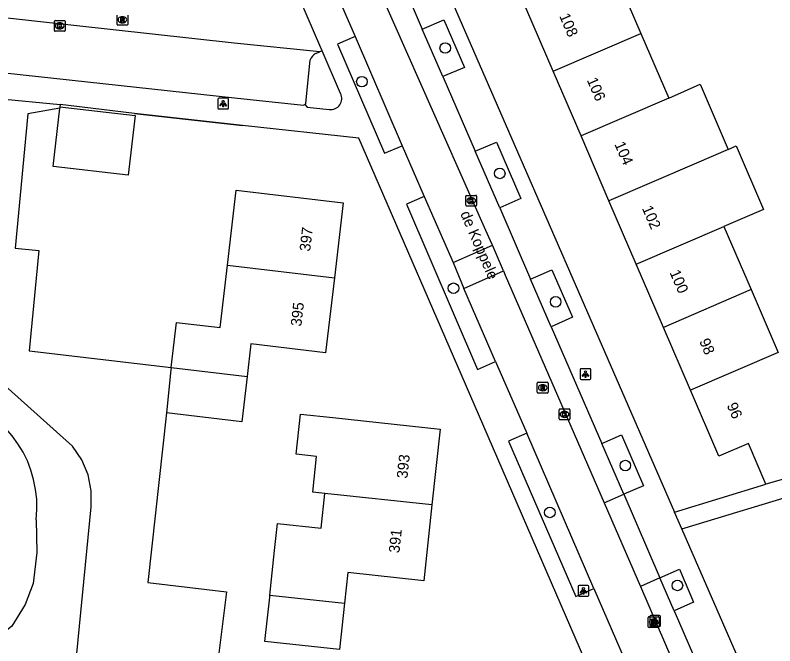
# Model space of a CAD drawing. Extents: x 162026 to 163499, y 387297 to 388169.
# Drawn here: x 162170.5 to 162240.9, y 387854 to 387912.5 of the extents above; entities that cross this region are included whole.
import ezdxf

# ---------------------------------------------------------------- set-up
doc = ezdxf.new("R2010")
doc.units = 0
for name, color, linetype in [('IMGEO_Boom', 7, 'Continuous'), ('IMGEO_Groenvoorziening', 7, 'Continuous'), ('IMGEO_Hek', 7, 'Continuous'), ('IMGEO_Kolk', 7, 'Continuous'), ('IMGEO_Lichtpunt', 7, 'Continuous'), ('IMGEO_Loofbos', 7, 'Continuous'), ('IMGEO_Muur', 7, 'Continuous'), ('IMGEO_Openbare_ruimte_label', 7, 'Continuous'), ('IMGEO_Pand', 7, 'Continuous'), ('IMGEO_Pand_nummerreeks', 7, 'Continuous'), ('IMGEO_Parkeervlak_open', 7, 'Continuous'), ('IMGEO_Rijbaan_lokaal_open', 7, 'Continuous'), ('IMGEO_Rioolput', 7, 'Continuous'), ('IMGEO_Voetpad_open', 7, 'Continuous')]:
    doc.layers.add(name, color=color, linetype=linetype)

msp = doc.modelspace()

# ---------------------------------------------------------------- linework, layer by layer
at = {"layer": 'IMGEO_Boom'}
for centre in [(162210.37, 387909.425), (162202.657, 387906.315), (162215.422, 387897.813), (162211.139, 387887.172), (162220.596, 387885.913), (162227.054, 387870.742), (162220.056, 387866.404), (162231.871, 387859.638)]:
    msp.add_circle(centre, 0.489, dxfattribs=at)
at = {"layer": 'IMGEO_Groenvoorziening'}
msp.add_lwpolyline([(162172.49, 387865.726), (162172.557, 387862.689), (162172.219, 387859.818), (162171.487, 387857.876), (162170.249, 387855.878), (162168.898, 387854.809), (162167.66, 387854.33), (162165.971, 387854.049), (162164.205, 387854.58), (162159.985, 387857.131), (162158.082, 387859.64)], dxfattribs=at)
msp.add_arc((162162.017, 387866.938), 10.543, 353.39636, 73.61646, dxfattribs=at)
at = {"layer": 'IMGEO_Hek'}
msp.add_lwpolyline([(162174.684, 387903.845), (162171.728, 387903.331), (162170.556, 387890.887), (162172.727, 387890.683), (162171.85, 387881.372), (162184.987, 387879.827)], dxfattribs=at)
at = {"layer": 'IMGEO_Kolk'}
for p, q in [((162174.174, 387911.056), (162174.174, 387911.908)), ((162174.249, 387911.982), (162175.101, 387911.982)), ((162174.662, 387911.762), (162174.687, 387911.762)), ((162175.175, 387911.908), (162175.175, 387911.056)), ((162175.101, 387910.982), (162174.249, 387910.982)), ((162174.685, 387911.202), (162174.66, 387911.202)), ((162212.277, 387894.854), (162212.277, 387895.706)), ((162212.352, 387895.78), (162213.204, 387895.78)), ((162212.765, 387895.56), (162212.79, 387895.56)), ((162213.278, 387895.706), (162213.278, 387894.854)), ((162213.204, 387894.78), (162212.352, 387894.78)), ((162212.788, 387895), (162212.763, 387895)), ((162220.917, 387875.059), (162220.917, 387875.911)), ((162220.992, 387875.985), (162221.844, 387875.985)), ((162221.405, 387875.765), (162221.43, 387875.765)), ((162221.918, 387875.911), (162221.918, 387875.059)), ((162221.844, 387874.985), (162220.992, 387874.985)), ((162221.428, 387875.205), (162221.403, 387875.205)), ((162229.171, 387855.813), (162229.171, 387856.665)), ((162229.246, 387856.739), (162230.098, 387856.739)), ((162230.172, 387856.665), (162230.172, 387855.813)), ((162229.659, 387856.519), (162229.684, 387856.519)), ((162230.098, 387855.739), (162229.246, 387855.739)), ((162229.682, 387855.959), (162229.657, 387855.959))]:
    msp.add_line(p, q, dxfattribs=at)
for points in [[(162174.174, 387911.056), (162174.174, 387911.908)], [(162174.249, 387911.982), (162175.101, 387911.982)], [(162174.495, 387911.682), (162174.618, 387911.682), (162174.618, 387911.531), (162174.748, 387911.682), (162174.912, 387911.682), (162174.766, 387911.531), (162174.919, 387911.282), (162174.767, 387911.282), (162174.682, 387911.446), (162174.618, 387911.379), (162174.618, 387911.282), (162174.495, 387911.282), (162174.495, 387911.682)], [(162175.175, 387911.908), (162175.175, 387911.056)], [(162175.101, 387910.982), (162174.249, 387910.982)], [(162212.277, 387894.854), (162212.277, 387895.706)], [(162212.352, 387895.78), (162213.204, 387895.78)], [(162212.598, 387895.48), (162212.721, 387895.48), (162212.721, 387895.329), (162212.851, 387895.48), (162213.015, 387895.48), (162212.869, 387895.329), (162213.022, 387895.08), (162212.87, 387895.08), (162212.785, 387895.244), (162212.721, 387895.177), (162212.721, 387895.08), (162212.598, 387895.08), (162212.598, 387895.48)], [(162213.278, 387895.706), (162213.278, 387894.854)], [(162213.204, 387894.78), (162212.352, 387894.78)], [(162220.917, 387875.059), (162220.917, 387875.911)], [(162220.992, 387875.985), (162221.844, 387875.985)], [(162221.238, 387875.685), (162221.361, 387875.685), (162221.361, 387875.534), (162221.491, 387875.685), (162221.655, 387875.685), (162221.509, 387875.534), (162221.662, 387875.285), (162221.51, 387875.285), (162221.425, 387875.449), (162221.361, 387875.382), (162221.361, 387875.285), (162221.238, 387875.285), (162221.238, 387875.685)], [(162221.918, 387875.911), (162221.918, 387875.059)], [(162221.844, 387874.985), (162220.992, 387874.985)], [(162229.171, 387855.813), (162229.171, 387856.665)], [(162229.246, 387856.739), (162230.098, 387856.739)], [(162230.172, 387856.665), (162230.172, 387855.813)], [(162229.492, 387856.439), (162229.615, 387856.439), (162229.615, 387856.288), (162229.745, 387856.439), (162229.909, 387856.439), (162229.763, 387856.288), (162229.916, 387856.039), (162229.764, 387856.039), (162229.679, 387856.203), (162229.615, 387856.136), (162229.615, 387856.039), (162229.492, 387856.039), (162229.492, 387856.439)], [(162230.098, 387855.739), (162229.246, 387855.739)]]:
    msp.add_lwpolyline(points, dxfattribs=at)
for centre, start, end in [((162174.251, 387911.906), 91.55205, 178.44795), ((162174.251, 387911.906), 91.55205, 178.44795), ((162175.099, 387911.906), 1.55205, 88.44795), ((162175.099, 387911.906), 1.55205, 88.44795), ((162174.251, 387911.058), 181.55205, 268.44795), ((162174.251, 387911.058), 181.55205, 268.44795), ((162175.099, 387911.058), 271.55205, 358.44795), ((162175.099, 387911.058), 271.55205, 358.44795), ((162212.354, 387895.704), 91.55205, 178.44795), ((162212.354, 387895.704), 91.55205, 178.44795), ((162213.202, 387895.704), 1.55205, 88.44795), ((162213.202, 387895.704), 1.55205, 88.44795), ((162212.354, 387894.856), 181.55205, 268.44795), ((162212.354, 387894.856), 181.55205, 268.44795), ((162213.202, 387894.856), 271.55205, 358.44795), ((162213.202, 387894.856), 271.55205, 358.44795), ((162220.994, 387875.909), 91.55205, 178.44795), ((162220.994, 387875.909), 91.55205, 178.44795), ((162221.842, 387875.909), 1.55205, 88.44795), ((162221.842, 387875.909), 1.55205, 88.44795), ((162220.994, 387875.061), 181.55205, 268.44795), ((162220.994, 387875.061), 181.55205, 268.44795), ((162221.842, 387875.061), 271.55205, 358.44795), ((162221.842, 387875.061), 271.55205, 358.44795), ((162229.248, 387856.663), 91.55205, 178.44795), ((162229.248, 387856.663), 91.55205, 178.44795), ((162230.096, 387856.663), 1.55205, 88.44795), ((162230.096, 387856.663), 1.55205, 88.44795), ((162229.248, 387855.815), 181.55205, 268.44795), ((162229.248, 387855.815), 181.55205, 268.44795), ((162230.096, 387855.815), 271.55205, 358.44795), ((162230.096, 387855.815), 271.55205, 358.44795)]:
    msp.add_arc(centre, 0.0765, start, end, dxfattribs=at)
for centre, major_axis, ratio, start_param, end_param in [((162174.661, 387911.482), (-0.387, 0.002), 0.722429, 4.712389, 7.853982), ((162174.686, 387911.482), (-0.39, 0.002), 0.717154, 1.570796, 4.712389), ((162212.764, 387895.28), (-0.387, 0.002), 0.722429, 4.712389, 7.853982), ((162212.789, 387895.28), (-0.39, 0.002), 0.717154, 1.570796, 4.712389), ((162221.404, 387875.485), (-0.387, 0.002), 0.722429, 4.712389, 7.853982), ((162221.429, 387875.485), (-0.39, 0.002), 0.717154, 1.570796, 4.712389), ((162229.658, 387856.239), (-0.387, 0.002), 0.722429, 4.712389, 7.853982), ((162229.683, 387856.239), (-0.39, 0.002), 0.717154, 1.570796, 4.712389)]:
    msp.add_ellipse(centre, major_axis=major_axis, ratio=ratio, start_param=start_param, end_param=end_param, dxfattribs=at)
at = {"layer": 'IMGEO_Lichtpunt'}
for p, q in [((162189.307, 387904.683), (162189.307, 387903.876)), ((162189.307, 387904.683), (162189.307, 387903.876)), ((162190.209, 387904.778), (162189.401, 387904.778)), ((162190.209, 387904.778), (162189.401, 387904.778)), ((162190.303, 387903.876), (162190.303, 387904.683)), ((162190.303, 387903.876), (162190.303, 387904.683)), ((162189.401, 387903.782), (162190.209, 387903.782)), ((162189.401, 387903.782), (162190.209, 387903.782)), ((162222.858, 387879.624), (162222.858, 387878.817)), ((162222.858, 387879.624), (162222.858, 387878.817)), ((162223.76, 387879.719), (162222.952, 387879.719)), ((162223.76, 387879.719), (162222.952, 387879.719)), ((162223.854, 387878.817), (162223.854, 387879.624)), ((162223.854, 387878.817), (162223.854, 387879.624)), ((162222.952, 387878.723), (162223.76, 387878.723)), ((162222.952, 387878.723), (162223.76, 387878.723)), ((162222.669, 387859.542), (162222.669, 387858.735)), ((162222.669, 387859.542), (162222.669, 387858.735)), ((162223.571, 387859.637), (162222.763, 387859.637)), ((162223.571, 387859.637), (162222.763, 387859.637)), ((162223.665, 387858.735), (162223.665, 387859.542)), ((162223.665, 387858.735), (162223.665, 387859.542)), ((162222.763, 387858.641), (162223.571, 387858.641)), ((162222.763, 387858.641), (162223.571, 387858.641)), ((162229.318, 387856.751), (162229.318, 387855.944)), ((162229.318, 387856.751), (162229.318, 387855.944)), ((162230.22, 387856.846), (162229.412, 387856.846)), ((162230.22, 387856.846), (162229.412, 387856.846)), ((162230.314, 387855.944), (162230.314, 387856.751)), ((162230.314, 387855.944), (162230.314, 387856.751)), ((162229.412, 387855.85), (162230.22, 387855.85)), ((162229.412, 387855.85), (162230.22, 387855.85))]:
    msp.add_line(p, q, dxfattribs=at)
for points in [[(162189.681, 387904.347), (162189.72, 387904.319), (162189.532, 387904.057), (162189.494, 387904.084), (162189.681, 387904.347)], [(162189.783, 387904.299), (162189.83, 387904.299), (162189.83, 387903.977), (162189.783, 387903.977), (162189.783, 387904.299)], [(162189.893, 387904.319), (162189.931, 387904.346), (162190.118, 387904.084), (162190.079, 387904.056), (162189.893, 387904.319)], [(162223.232, 387879.288), (162223.271, 387879.26), (162223.083, 387878.998), (162223.045, 387879.025), (162223.232, 387879.288)], [(162223.334, 387879.24), (162223.381, 387879.24), (162223.381, 387878.918), (162223.334, 387878.918), (162223.334, 387879.24)], [(162223.444, 387879.26), (162223.482, 387879.287), (162223.669, 387879.025), (162223.63, 387878.997), (162223.444, 387879.26)], [(162223.043, 387859.206), (162223.082, 387859.178), (162222.894, 387858.916), (162222.856, 387858.943), (162223.043, 387859.206)], [(162223.145, 387859.158), (162223.192, 387859.158), (162223.192, 387858.836), (162223.145, 387858.836), (162223.145, 387859.158)], [(162223.255, 387859.178), (162223.293, 387859.205), (162223.48, 387858.943), (162223.441, 387858.915), (162223.255, 387859.178)], [(162229.692, 387856.415), (162229.731, 387856.387), (162229.543, 387856.125), (162229.505, 387856.152), (162229.692, 387856.415)], [(162229.794, 387856.367), (162229.841, 387856.367), (162229.841, 387856.045), (162229.794, 387856.045), (162229.794, 387856.367)], [(162229.904, 387856.387), (162229.942, 387856.414), (162230.129, 387856.152), (162230.09, 387856.124), (162229.904, 387856.387)]]:
    msp.add_lwpolyline(points, dxfattribs=at)
for centre in [(162189.806, 387904.481), (162223.357, 387879.422), (162223.168, 387859.34), (162229.817, 387856.549)]:
    msp.add_circle(centre, 0.0994, dxfattribs=at)
for centre, start, end in [((162189.401, 387904.683), 90, 180), ((162189.401, 387904.683), 90, 180), ((162190.209, 387904.683), 0, 90), ((162190.209, 387904.683), 0, 90), ((162189.401, 387903.876), 180, 270), ((162189.401, 387903.876), 180, 270), ((162190.209, 387903.876), 270, 0), ((162190.209, 387903.876), 270, 360), ((162222.952, 387879.624), 90, 180), ((162222.952, 387879.624), 90, 180), ((162223.76, 387879.624), 0, 90), ((162223.76, 387879.624), 0, 90), ((162222.952, 387878.817), 180, 270), ((162222.952, 387878.817), 180, 270), ((162223.76, 387878.817), 270, 0), ((162223.76, 387878.817), 270, 360), ((162222.763, 387859.542), 90, 180), ((162222.763, 387859.542), 90, 180), ((162223.571, 387859.542), 0, 90), ((162223.571, 387859.542), 0, 90), ((162222.763, 387858.735), 180, 270), ((162222.763, 387858.735), 180, 270), ((162223.571, 387858.735), 270, 0), ((162223.571, 387858.735), 270, 360), ((162229.412, 387856.751), 90, 180), ((162229.412, 387856.751), 90, 180), ((162230.22, 387856.751), 0, 90), ((162230.22, 387856.751), 0, 90), ((162229.412, 387855.944), 180, 270), ((162229.412, 387855.944), 180, 270), ((162230.22, 387855.944), 270, 0), ((162230.22, 387855.944), 270, 360)]:
    msp.add_arc(centre, 0.0946, start, end, dxfattribs=at)
at = {"layer": 'IMGEO_Loofbos'}
for points in [[(162174.684, 387903.845), (162171.728, 387903.331), (162170.556, 387890.887), (162172.727, 387890.683), (162171.85, 387881.372), (162184.987, 387879.827)], [(162174.719, 387904.201), (162174.697, 387903.966)], [(162175.011, 387840.691), (162177.571, 387866.907), (162177.598, 387868.402), (162177.312, 387869.89), (162176.723, 387871.285), (162175.856, 387872.528), (162167.785, 387879.745), (162165.386, 387881.891)], [(162184.551, 387875.63), (162182.846, 387859.915), (162190.113, 387859.038), (162188.873, 387849.177), (162191.3, 387848.871), (162190.097, 387839.307), (162191.913, 387839.079), (162203.311, 387837.645)]]:
    msp.add_lwpolyline(points, dxfattribs=at)
at = {"layer": 'IMGEO_Muur'}
msp.add_lwpolyline([(162181.596, 387903.362), (162191.595, 387902.255)], dxfattribs=at)
at = {"layer": 'IMGEO_Pand'}
for points in [[(162225.961, 387916.658), (162228.49, 387910.779)], [(162220.369, 387907.286), (162217.84, 387913.165)], [(162220.369, 387907.286), (162228.49, 387910.779)], [(162228.49, 387910.779), (162231.07, 387904.779)], [(162222.949, 387901.286), (162220.369, 387907.286)], [(162231.07, 387904.779), (162233.982, 387906.073), (162236.58, 387900.035)], [(162231.07, 387904.779), (162222.949, 387901.286)], [(162174.697, 387903.966), (162181.653, 387903.177), (162181.026, 387897.657), (162174.071, 387898.446), (162174.684, 387903.845)], [(162174.697, 387903.966), (162174.684, 387903.845)], [(162225.531, 387895.282), (162222.949, 387901.286)], [(162236.58, 387900.035), (162237.322, 387900.354), (162239.85, 387894.475), (162236.18, 387892.897)], [(162236.58, 387900.035), (162233.652, 387898.775), (162225.531, 387895.282)], [(162190.202, 387889.31), (162191.018, 387896.259), (162200.93, 387895.094), (162200.114, 387888.148)], [(162228.059, 387889.405), (162225.531, 387895.282)], [(162228.059, 387889.405), (162236.18, 387892.897)], [(162236.18, 387892.897), (162238.698, 387887.042)], [(162184.987, 387879.827), (162185.479, 387884.009), (162189.523, 387883.534), (162190.202, 387889.31)], [(162190.202, 387889.31), (162200.114, 387888.148)], [(162230.578, 387883.548), (162228.059, 387889.405)], [(162200.114, 387888.148), (162199.298, 387881.2), (162192.383, 387882.012), (162192.029, 387878.999)], [(162238.698, 387887.042), (162230.578, 387883.548)], [(162238.698, 387887.042), (162241.202, 387881.22)], [(162233.081, 387877.727), (162230.578, 387883.548)], [(162241.202, 387881.22), (162233.081, 387877.727)], [(162184.987, 387879.827), (162184.963, 387879.62), (162184.551, 387875.63)], [(162184.987, 387879.827), (162192.029, 387878.999)], [(162192.029, 387878.999), (162191.536, 387874.81), (162184.551, 387875.63)], [(162240.067, 387869.028), (162238.451, 387872.785), (162235.713, 387871.608), (162233.081, 387877.727)], [(162199.216, 387868.166), (162198.101, 387868.286), (162198.455, 387871.588), (162196.578, 387871.789), (162196.977, 387875.508), (162199.969, 387875.187), (162209.893, 387874.123), (162209.141, 387867.102)], [(162248.629, 387871.455), (162240.067, 387869.028)], [(162194.134, 387858.736), (162194.577, 387862.866), (162194.848, 387865.392), (162198.873, 387864.96), (162199.216, 387868.166)], [(162209.141, 387867.102), (162199.216, 387868.166)], [(162209.141, 387867.102), (162208.388, 387860.08), (162201.339, 387860.836), (162201.035, 387857.999)], [(162201.035, 387857.999), (162200.573, 387853.691), (162193.673, 387854.43), (162194.115, 387858.555), (162194.134, 387858.736)], [(162194.134, 387858.736), (162201.035, 387857.999)]]:
    msp.add_lwpolyline(points, dxfattribs=at)
at = {"layer": 'IMGEO_Parkeervlak_open'}
for points in [[(162210.149, 387906.788), (162208.23, 387911.16)], [(162198.36, 387908.911), (162198.769, 387909.076)], [(162197.451, 387904.299), (162197.877, 387908.337)], [(162215.43, 387894.623), (162213.151, 387899.869)], [(162220.187, 387883.585), (162218.278, 387888)], [(162226.899, 387868.081), (162224.859, 387872.782)], [(162231.569, 387857.298), (162230.255, 387860.338)]]:
    msp.add_lwpolyline(points, dxfattribs=at)
for centre, radius, start, end in [((162198.882, 387907.981), 1.067, 119.33136, 160.50988), ((162197.197, 387904.416), 0.279, 304.63196, 335.25997)]:
    msp.add_arc(centre, radius, start, end, dxfattribs=at)
at = {"layer": 'IMGEO_Rijbaan_lokaal_open'}
for points in [[(162214.74, 387891.15), (162214.557, 387891.577), (162214.133, 387892.535), (162201.966, 387919.996)], [(162199.391, 387916.6), (162202.039, 387910.495)], [(162198.98, 387909.164), (162198.763, 387909.668), (162196.417, 387915.126)], [(162198.769, 387909.076), (162190.839, 387909.893), (162164.457, 387912.774)], [(162202.039, 387910.495), (162206.391, 387900.374)], [(162198.98, 387909.164), (162198.769, 387909.076)], [(162206.391, 387900.374), (162208.436, 387895.684)], [(162208.436, 387895.684), (162211.1, 387889.572)], [(162211.1, 387889.572), (162214.74, 387891.15)], [(162215.753, 387888.784), (162214.74, 387891.15)], [(162211.1, 387889.572), (162212.088, 387887.135)], [(162212.088, 387887.135), (162215.753, 387888.784)], [(162215.753, 387888.784), (162215.926, 387888.379), (162225.079, 387867.284)], [(162215.031, 387880.388), (162212.088, 387887.135)], [(162215.031, 387880.388), (162217.932, 387873.737)], [(162224.144, 387859.344), (162217.932, 387873.737)], [(162225.079, 387867.284), (162226.899, 387868.081)], [(162226.899, 387868.081), (162230.255, 387860.338)], [(162225.079, 387867.284), (162228.452, 387859.53)], [(162230.255, 387860.338), (162228.452, 387859.53)], [(162228.452, 387859.53), (162238.031, 387837.33)], [(162224.144, 387859.344), (162227.027, 387852.664)]]:
    msp.add_lwpolyline(points, dxfattribs=at)
at = {"layer": 'IMGEO_Rioolput'}
for p, q in [((162179.977, 387911.618), (162179.977, 387912.47)), ((162180.465, 387912.324), (162180.49, 387912.324)), ((162180.978, 387912.47), (162180.978, 387911.618)), ((162180.904, 387911.544), (162180.052, 387911.544)), ((162180.488, 387911.764), (162180.463, 387911.764)), ((162218.9, 387877.53), (162218.9, 387878.382)), ((162218.975, 387878.456), (162219.827, 387878.456)), ((162219.388, 387878.236), (162219.413, 387878.236)), ((162219.901, 387878.382), (162219.901, 387877.53)), ((162219.827, 387877.456), (162218.975, 387877.456)), ((162219.411, 387877.676), (162219.386, 387877.676))]:
    msp.add_line(p, q, dxfattribs=at)
for points in [[(162179.977, 387911.618), (162179.977, 387912.47)], [(162180.566, 387912.242), (162180.314, 387912.244), (162180.314, 387911.844)], [(162180.978, 387912.47), (162180.978, 387911.618)], [(162180.904, 387911.544), (162180.052, 387911.544)], [(162180.314, 387911.844), (162180.438, 387911.844), (162180.438, 387912.006), (162180.449, 387912.006)], [(162180.492, 387912.163), (162180.438, 387912.163), (162180.438, 387912.082)], [(162180.438, 387912.082), (162180.49, 387912.082)], [(162180.496, 387911.977), (162180.567, 387911.844), (162180.707, 387911.844), (162180.642, 387911.97)], [(162218.9, 387877.53), (162218.9, 387878.382)], [(162218.975, 387878.456), (162219.827, 387878.456)], [(162219.489, 387878.154), (162219.237, 387878.156), (162219.237, 387877.756)], [(162219.237, 387877.756), (162219.361, 387877.756), (162219.361, 387877.918), (162219.372, 387877.918)], [(162219.415, 387878.075), (162219.361, 387878.075), (162219.361, 387877.994)], [(162219.361, 387877.994), (162219.413, 387877.994)], [(162219.419, 387877.889), (162219.49, 387877.756), (162219.63, 387877.756), (162219.565, 387877.882)], [(162219.901, 387878.382), (162219.901, 387877.53)], [(162219.827, 387877.456), (162218.975, 387877.456)]]:
    msp.add_lwpolyline(points, dxfattribs=at)
for centre, radius, start, end in [((162180.565, 387912.132), 0.109, 350.36119, 89.41601), ((162180.054, 387911.62), 0.0765, 181.55205, 268.44795), ((162180.054, 387911.62), 0.0765, 181.55205, 268.44795), ((162180.448, 387911.953), 0.0533, 26.02933, 88.69889), ((162180.474, 387912.271), 0.19, 274.7715, 282.96867), ((162180.498, 387912.067), 0.0964, 77.00612, 93.18647), ((162180.512, 387912.124), 0.0378, 276.66336, 79.67722), ((162180.563, 387912.132), 0.112, 277.58423, 350.98172), ((162180.547, 387911.917), 0.108, 29.51342, 73.79051), ((162180.902, 387911.62), 0.0765, 271.55205, 358.44795), ((162180.902, 387911.62), 0.0765, 271.55205, 358.44795), ((162218.977, 387878.38), 0.0765, 91.55205, 178.44795), ((162218.977, 387878.38), 0.0765, 91.55205, 178.44795), ((162219.371, 387877.865), 0.0533, 26.02933, 88.69889), ((162219.397, 387878.183), 0.19, 274.7715, 282.96867), ((162219.421, 387877.979), 0.0964, 77.00612, 93.18647), ((162219.435, 387878.036), 0.0378, 276.66336, 79.67722), ((162219.488, 387878.044), 0.109, 350.36119, 89.41601), ((162219.486, 387878.044), 0.112, 277.58423, 350.98172), ((162219.47, 387877.829), 0.108, 29.51342, 73.79051), ((162219.825, 387878.38), 0.0765, 1.55205, 88.44795), ((162219.825, 387878.38), 0.0765, 1.55205, 88.44795), ((162218.977, 387877.532), 0.0765, 181.55205, 268.44795), ((162218.977, 387877.532), 0.0765, 181.55205, 268.44795), ((162219.825, 387877.532), 0.0765, 271.55205, 358.44795), ((162219.825, 387877.532), 0.0765, 271.55205, 358.44795)]:
    msp.add_arc(centre, radius, start, end, dxfattribs=at)
for centre, major_axis, ratio, start_param, end_param in [((162180.464, 387912.044), (-0.387, 0.002), 0.722429, 4.712389, 7.853982), ((162180.489, 387912.044), (-0.39, 0.002), 0.717154, 1.570796, 4.712389), ((162219.387, 387877.956), (-0.387, 0.002), 0.722429, 4.712389, 7.853982), ((162219.412, 387877.956), (-0.39, 0.002), 0.717154, 1.570796, 4.712389)]:
    msp.add_ellipse(centre, major_axis=major_axis, ratio=ratio, start_param=start_param, end_param=end_param, dxfattribs=at)
at = {"layer": 'IMGEO_Voetpad_open'}
for points in [[(162205.445, 387926.498), (162231.603, 387866.429)], [(162205.968, 387916.454), (162208.23, 387911.16)], [(162208.23, 387911.16), (162210.241, 387912.052), (162212.142, 387907.612), (162210.149, 387906.788)], [(162202.039, 387910.495), (162200.396, 387909.773), (162204.739, 387899.677), (162206.391, 387900.374)], [(162200.687, 387905.213), (162198.98, 387909.164)], [(162165.031, 387907.626), (162190.861, 387904.827), (162197.233, 387904.14)], [(162210.149, 387906.788), (162213.151, 387899.869)], [(162168.92, 387904.753), (162174.719, 387904.201)], [(162228.688, 387831.187), (162228.98, 387831.332), (162229.259, 387831.503), (162229.521, 387831.698), (162229.764, 387831.915), (162229.987, 387832.154), (162230.188, 387832.411), (162230.366, 387832.685), (162230.518, 387832.974), (162230.643, 387833.276), (162230.741, 387833.587), (162230.811, 387833.906), (162230.852, 387834.23), (162230.864, 387834.557), (162230.847, 387834.883), (162230.801, 387835.206), (162230.726, 387835.524), (162230.623, 387835.833), (162230.561, 387835.984), (162213.439, 387875.511), (162202.371, 387901.061), (162191.595, 387902.255), (162181.596, 387903.362), (162174.719, 387904.201)], [(162197.356, 387904.186), (162197.581, 387903.95), (162199.637, 387903.743)], [(162213.151, 387899.869), (162215.128, 387900.695), (162217.38, 387895.491), (162215.43, 387894.623)], [(162208.436, 387895.684), (162206.787, 387894.965), (162213.36, 387879.645), (162215.031, 387880.388)], [(162215.43, 387894.623), (162218.278, 387888)], [(162218.278, 387888), (162220.244, 387888.884), (162222.164, 387884.48), (162220.187, 387883.585)], [(162220.187, 387883.585), (162224.859, 387872.782)], [(162217.932, 387873.737), (162216.236, 387872.997), (162222.47, 387858.614), (162224.144, 387859.344)], [(162224.859, 387872.782), (162226.693, 387873.584), (162228.724, 387868.882), (162226.899, 387868.081)], [(162231.603, 387866.429), (162240.067, 387869.028)], [(162232.282, 387864.869), (162244.103, 387868.45)], [(162232.282, 387864.869), (162231.603, 387866.429)], [(162241.346, 387844.054), (162232.282, 387864.869)], [(162230.255, 387860.338), (162232.072, 387861.151), (162233.378, 387858.093), (162231.569, 387857.298)], [(162231.569, 387857.298), (162235.158, 387849)]]:
    msp.add_lwpolyline(points, dxfattribs=at)
for centre, radius, start, end in [((162199.772, 387904.757), 1.023, 262.44194, 26.48271), ((162197.194, 387904.431), 0.294, 277.58904, 303.42091)]:
    msp.add_arc(centre, radius, start, end, dxfattribs=at)

# ---------------------------------------------------------------- texts
at = {"layer": 'IMGEO_Openbare_ruimte_label'}
msp.add_text('de Koppele', height=1, rotation=293.33404, dxfattribs=at).set_placement((162211.744, 387894.088))
at = {"layer": 'IMGEO_Pand_nummerreeks'}
for s, rotation, p in [('108', 293.27175, (162220.912, 387912.401)), ('106', 293.27175, (162223.466, 387906.462)), ('104', 293.27334, (162226.022, 387900.521)), ('102', 293.27334, (162228.576, 387894.582)), ('397', 83.30069, (162197.859, 387890.546)), ('100', 293.27175, (162231.133, 387888.636)), ('395', 83.30069, (162197.043, 387883.599)), ('98', 293.27175, (162233.87, 387882.272)), ('96', 293.27175, (162236.424, 387876.333)), ('393', 83.88102, (162206.864, 387869.51)), ('391', 83.88102, (162206.124, 387862.601))]:
    msp.add_text(s, height=1, rotation=rotation, dxfattribs=at).set_placement(p)

doc.saveas('drawing.dxf')
